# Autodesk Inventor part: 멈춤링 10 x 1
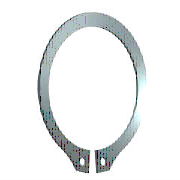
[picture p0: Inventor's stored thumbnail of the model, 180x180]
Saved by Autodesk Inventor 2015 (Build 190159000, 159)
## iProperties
IsCustomPart: 0
Created: 2009-02
Part Number: 멈춤링 10 x 1
Material: Steel, Mild
Description: 리테이닝 링(C형)
Document SubType Name: Modeling
Standard: KS B 1336
Designer: SeoGD™
Standards Organization: KS
Language: ko-KR
Size Designation: 10 x 1
Categories: <MemberInstance><Categories><Category DisplayName="샤프트 부품" InternalName="7f7aeb1f-a693-4053-b835-cee3144e0d98" Mnemonic="SHFT"><Category DisplayName="써클립" Inter
Density: 1 g/cm^3
Appearance: Metal-Steel
Author: SeoGD™
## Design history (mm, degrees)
sketch "스케치1"
  geometry: L1 (-6, 0)-(6, 0) reference; L2 (0, 20.189)-(0, -80.536) reference; L3 (-48.09, 0)-(48.09, 0) reference; L4 (-0.3, -9.791)-(-0.3, -12.791); L5 (-0.3, -6.54)-(-0.3, -13.29); L6 (-2.795, 1.6)-(3.672, 1.6); L7 (0.3, -6.54)-(0.3, -13.29); L8 (0.3, -9.791)-(0.3, -12.791); C1 r 0.6 at (-1.2, -11.486); C2 r 0.6 at (1.2, -11.486); A1 r 4.8 centre (0, -5) between (0.3, -9.791) and (-0.3, -9.791); A2 r 6.2 centre (0, -4.6) between (2.988, -10.033) and (-2.988, -10.033); A3 r 7.796 centre (0, -5) between (-1.418, -12.666) and (-0.3, -12.791); A4 r 1.2 centre (-1.2, -11.486) between (-2.383, -11.285) and (-1.418, -12.666); A5 r 1.2 centre (-3.566, -11.084) between (-2.383, -11.285) and (-2.988, -10.033); A6 r 1.2 centre (3.566, -11.084) between (2.988, -10.033) and (2.383, -11.285); A7 r 1.2 centre (1.2, -11.486) between (1.418, -12.666) and (2.383, -11.285); A8 r 7.796 centre (0, -5) between (0.3, -12.791) and (1.418, -12.666)
  constraints: 16 point on circle, 12 end point, 10 centre point, 9 symmetric about line, 5 point on line, 4 tangent, 3 coincident, 2 horizontal, 1 perpendicular, 1 vertical, 5 other
  dimensions: "d0" = 9.6 diameter of A1 (= ND); "d1" = 3 distance of L4.end L4.start (= SRB2); "d6" = 0.3 distance between parallel lines of L2 L5 (= 0.25 x SD5); "d7" = 1.6 distance between parallel lines of L6 L3 (= SRB1); "d8" = 0.4 distance of A1.centre A2.centre (= 0.25 x SRB1); "d9" = 1.2 radius of A4 (= SD5); "d10" = 1.2 radius of A5 (= SD5); "d11" = 0.9 distance from line of L4 A4.centre (= 0.75 x SD5); "d12" = 1.2 diameter of C1 (= SD5); "d13" = 1.2 diameter of C2 (= SD5); "d14" = 5 distance from line of A1.centre L1 (= 0.5 x WD)
extrude "본체" new body sketch "스케치1" distance "d2" = 1 (= SD); taper "d3" = 0 deg
workaxis "Work Axis1"
workplane "Work Plane1"
body "Solid1"
other parameters: "SD" = 1 [user parameter; used in 1 equation term], "SRB1" = 1.6 [user parameter; used in 2 equation terms], "ND" = 9.6 [user parameter; used in 1 equation term], "SRB2" = 3 [user parameter; used in 1 equation term], "SD5" = 1.2 [user parameter; used in 6 equation terms], "d15" = 0, "d16" = 0, "d17" = 0, "d41" = 0, "d42" = 0, "SD3" = 9.3 [user parameter], "WDMAX" = 11 [user parameter]
